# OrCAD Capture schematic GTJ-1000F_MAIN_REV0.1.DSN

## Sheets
1 00. INDEX
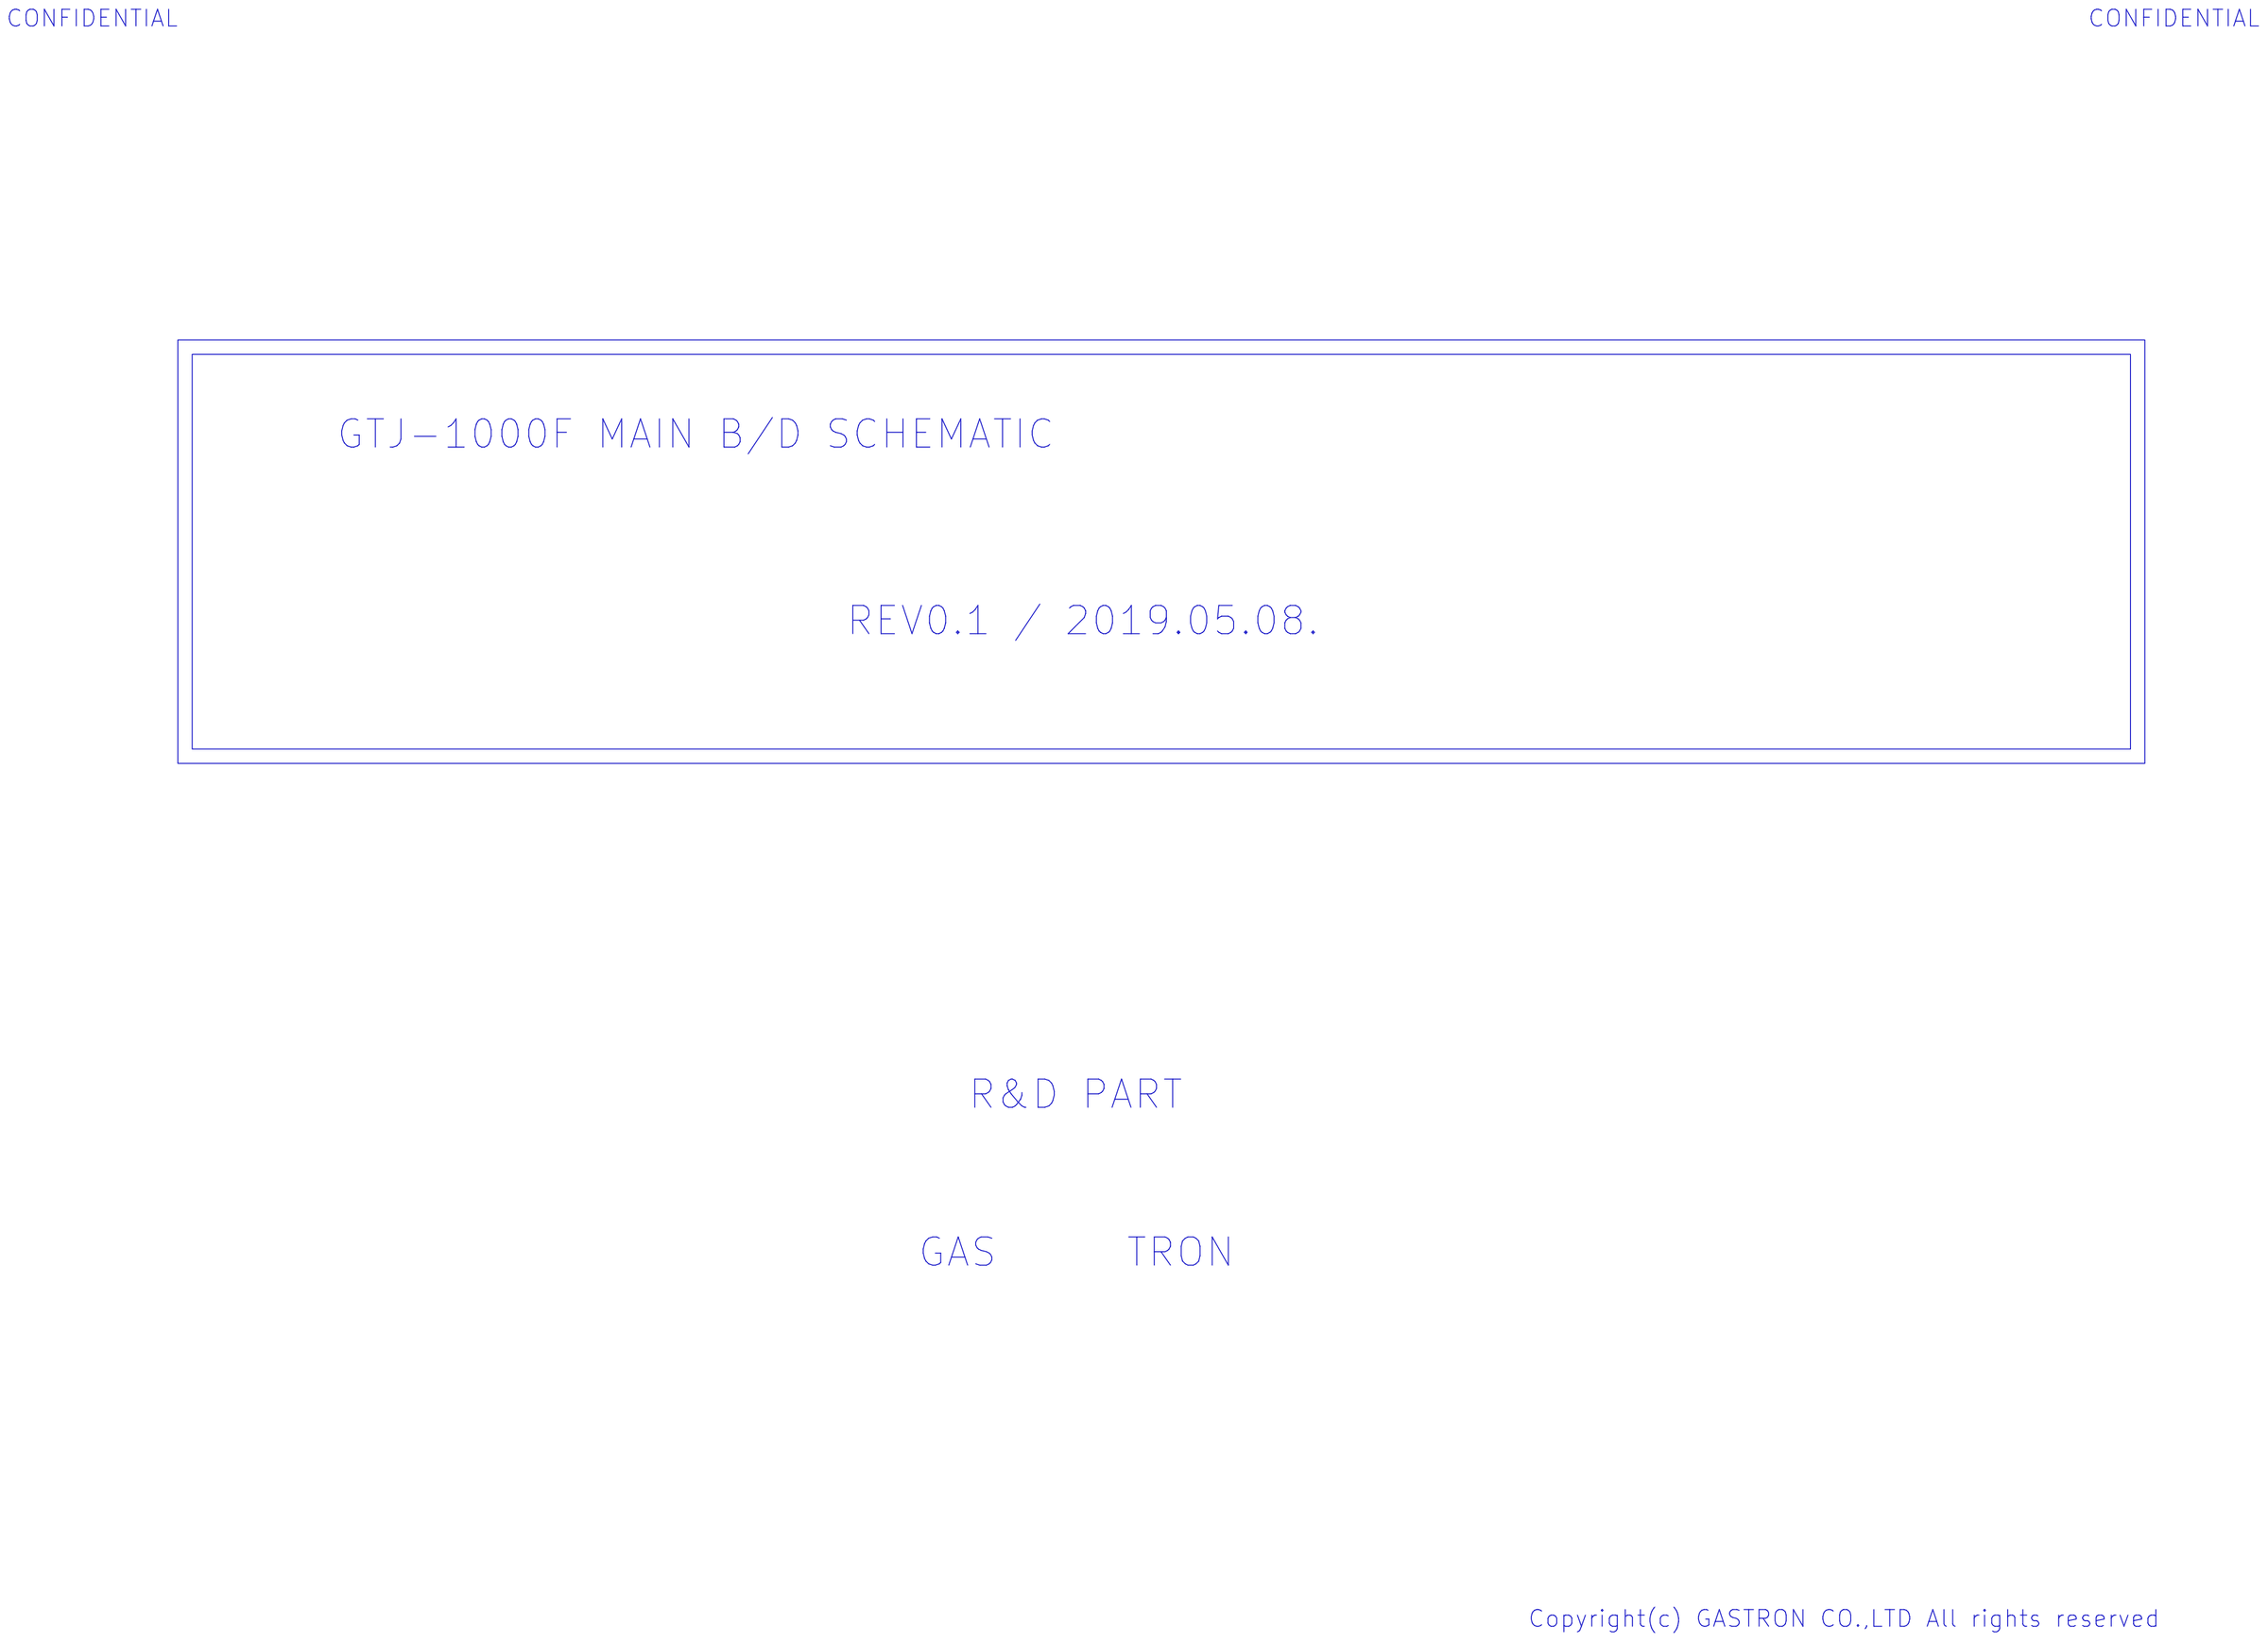
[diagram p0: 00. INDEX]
2 01. Power Supply: size A3; title: Power Supply; rev: 0.1
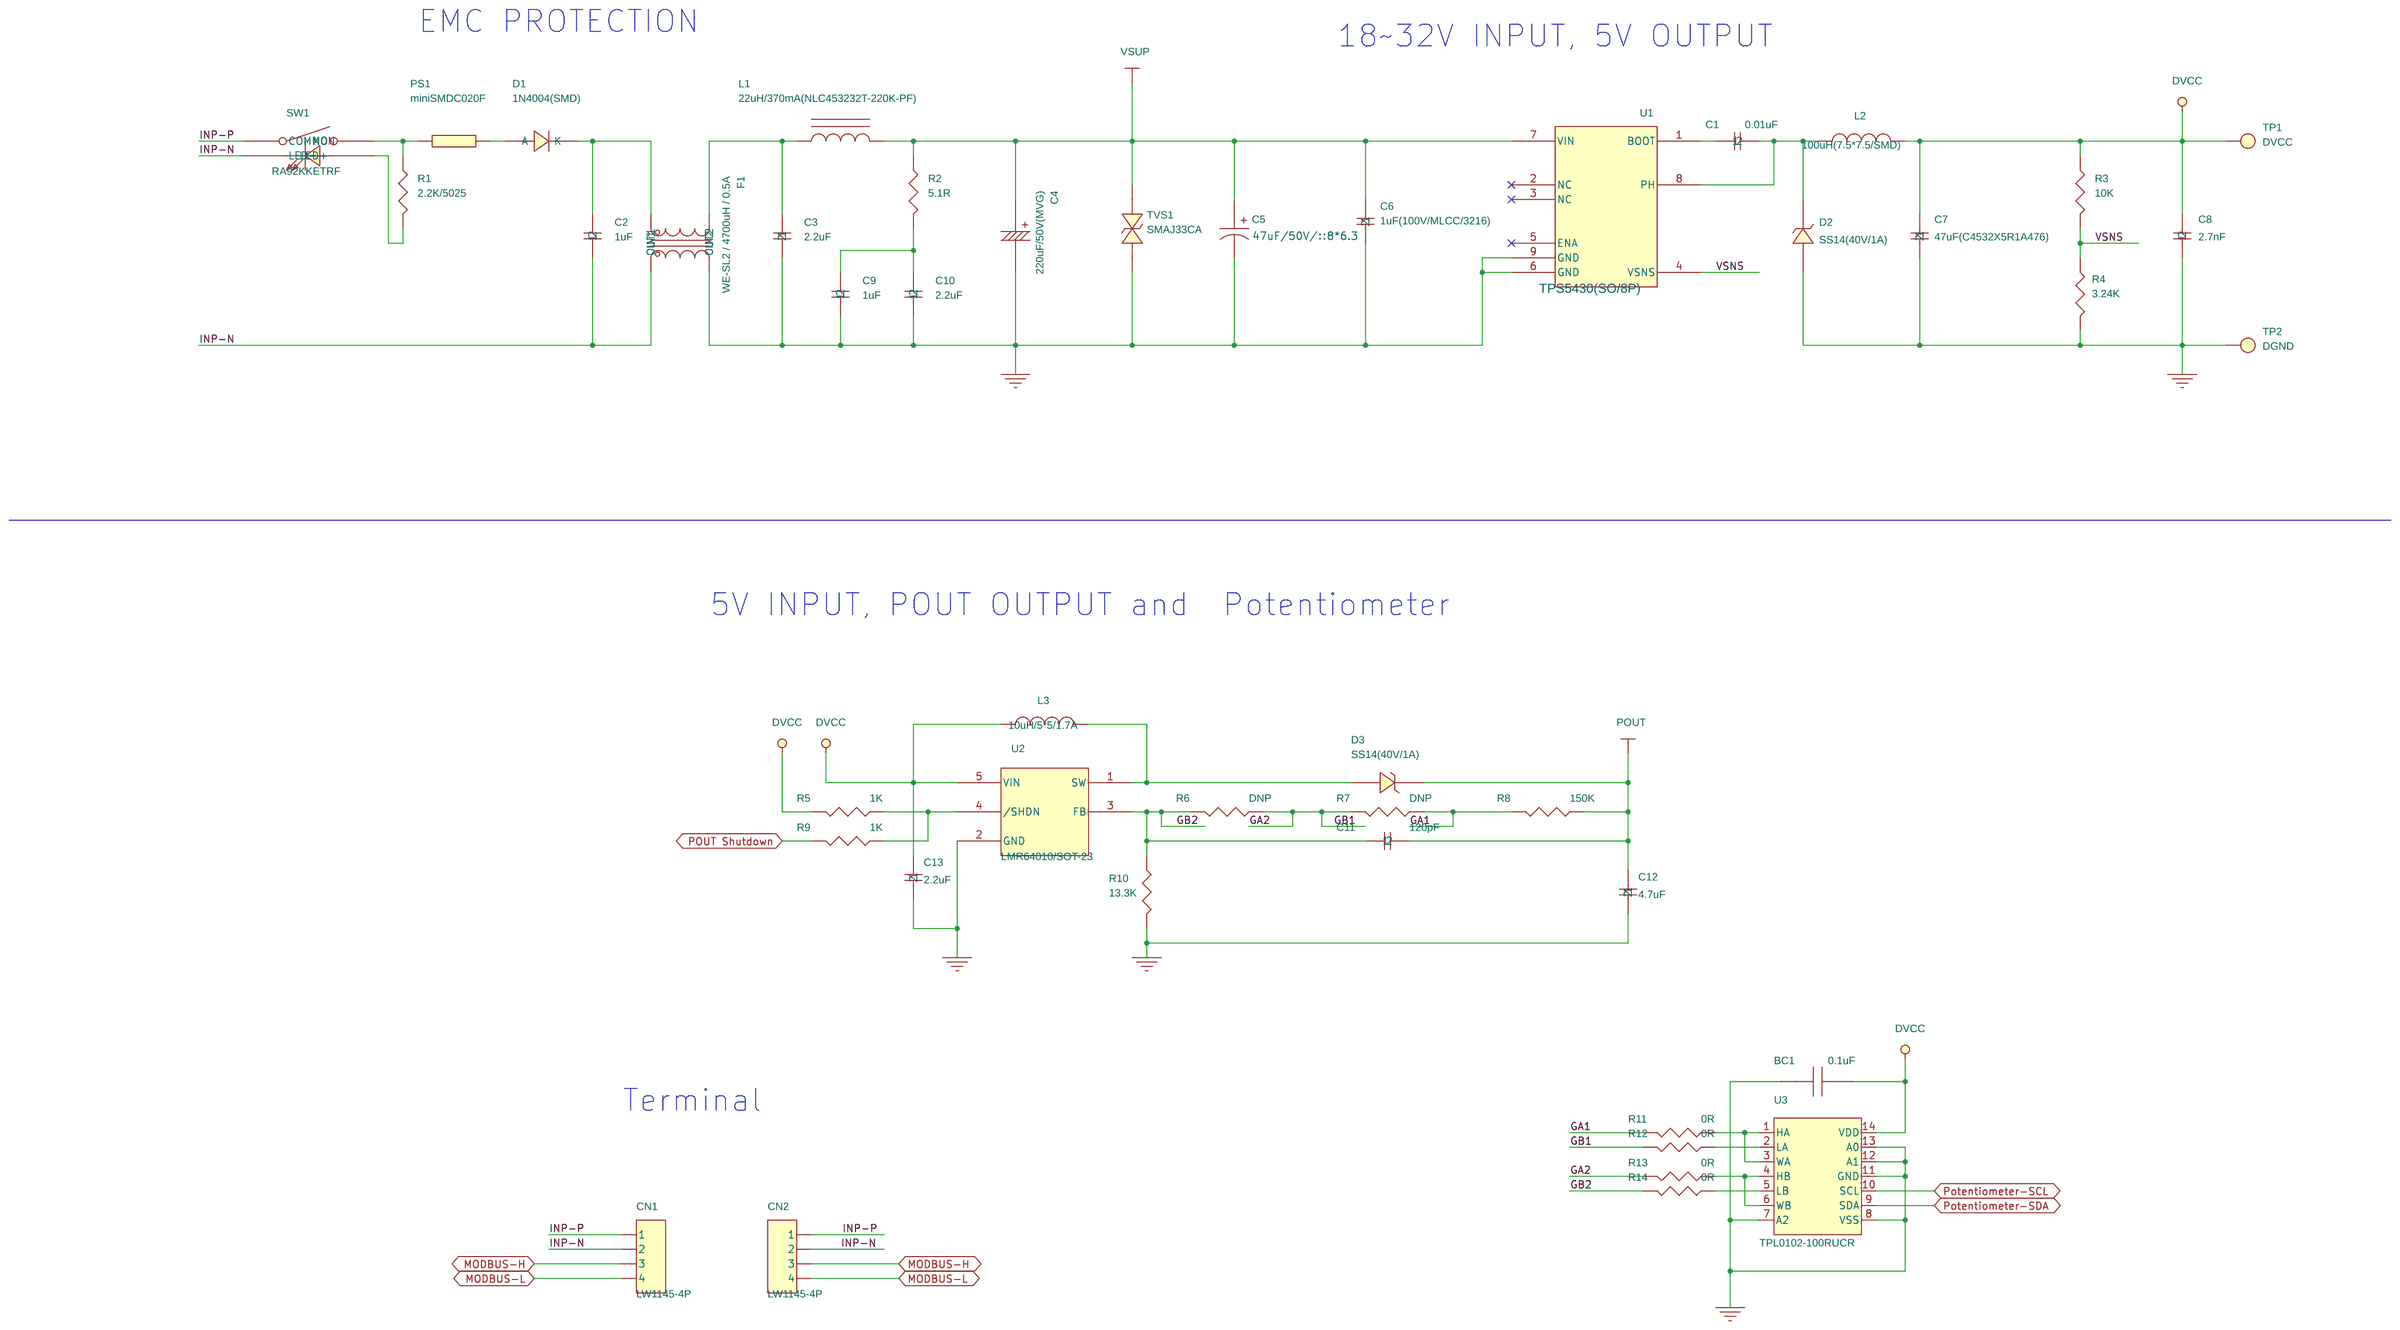
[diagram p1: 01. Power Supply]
3 02. MCU Peripheral: size A3; title: MCU Peripheral; rev: 0.1
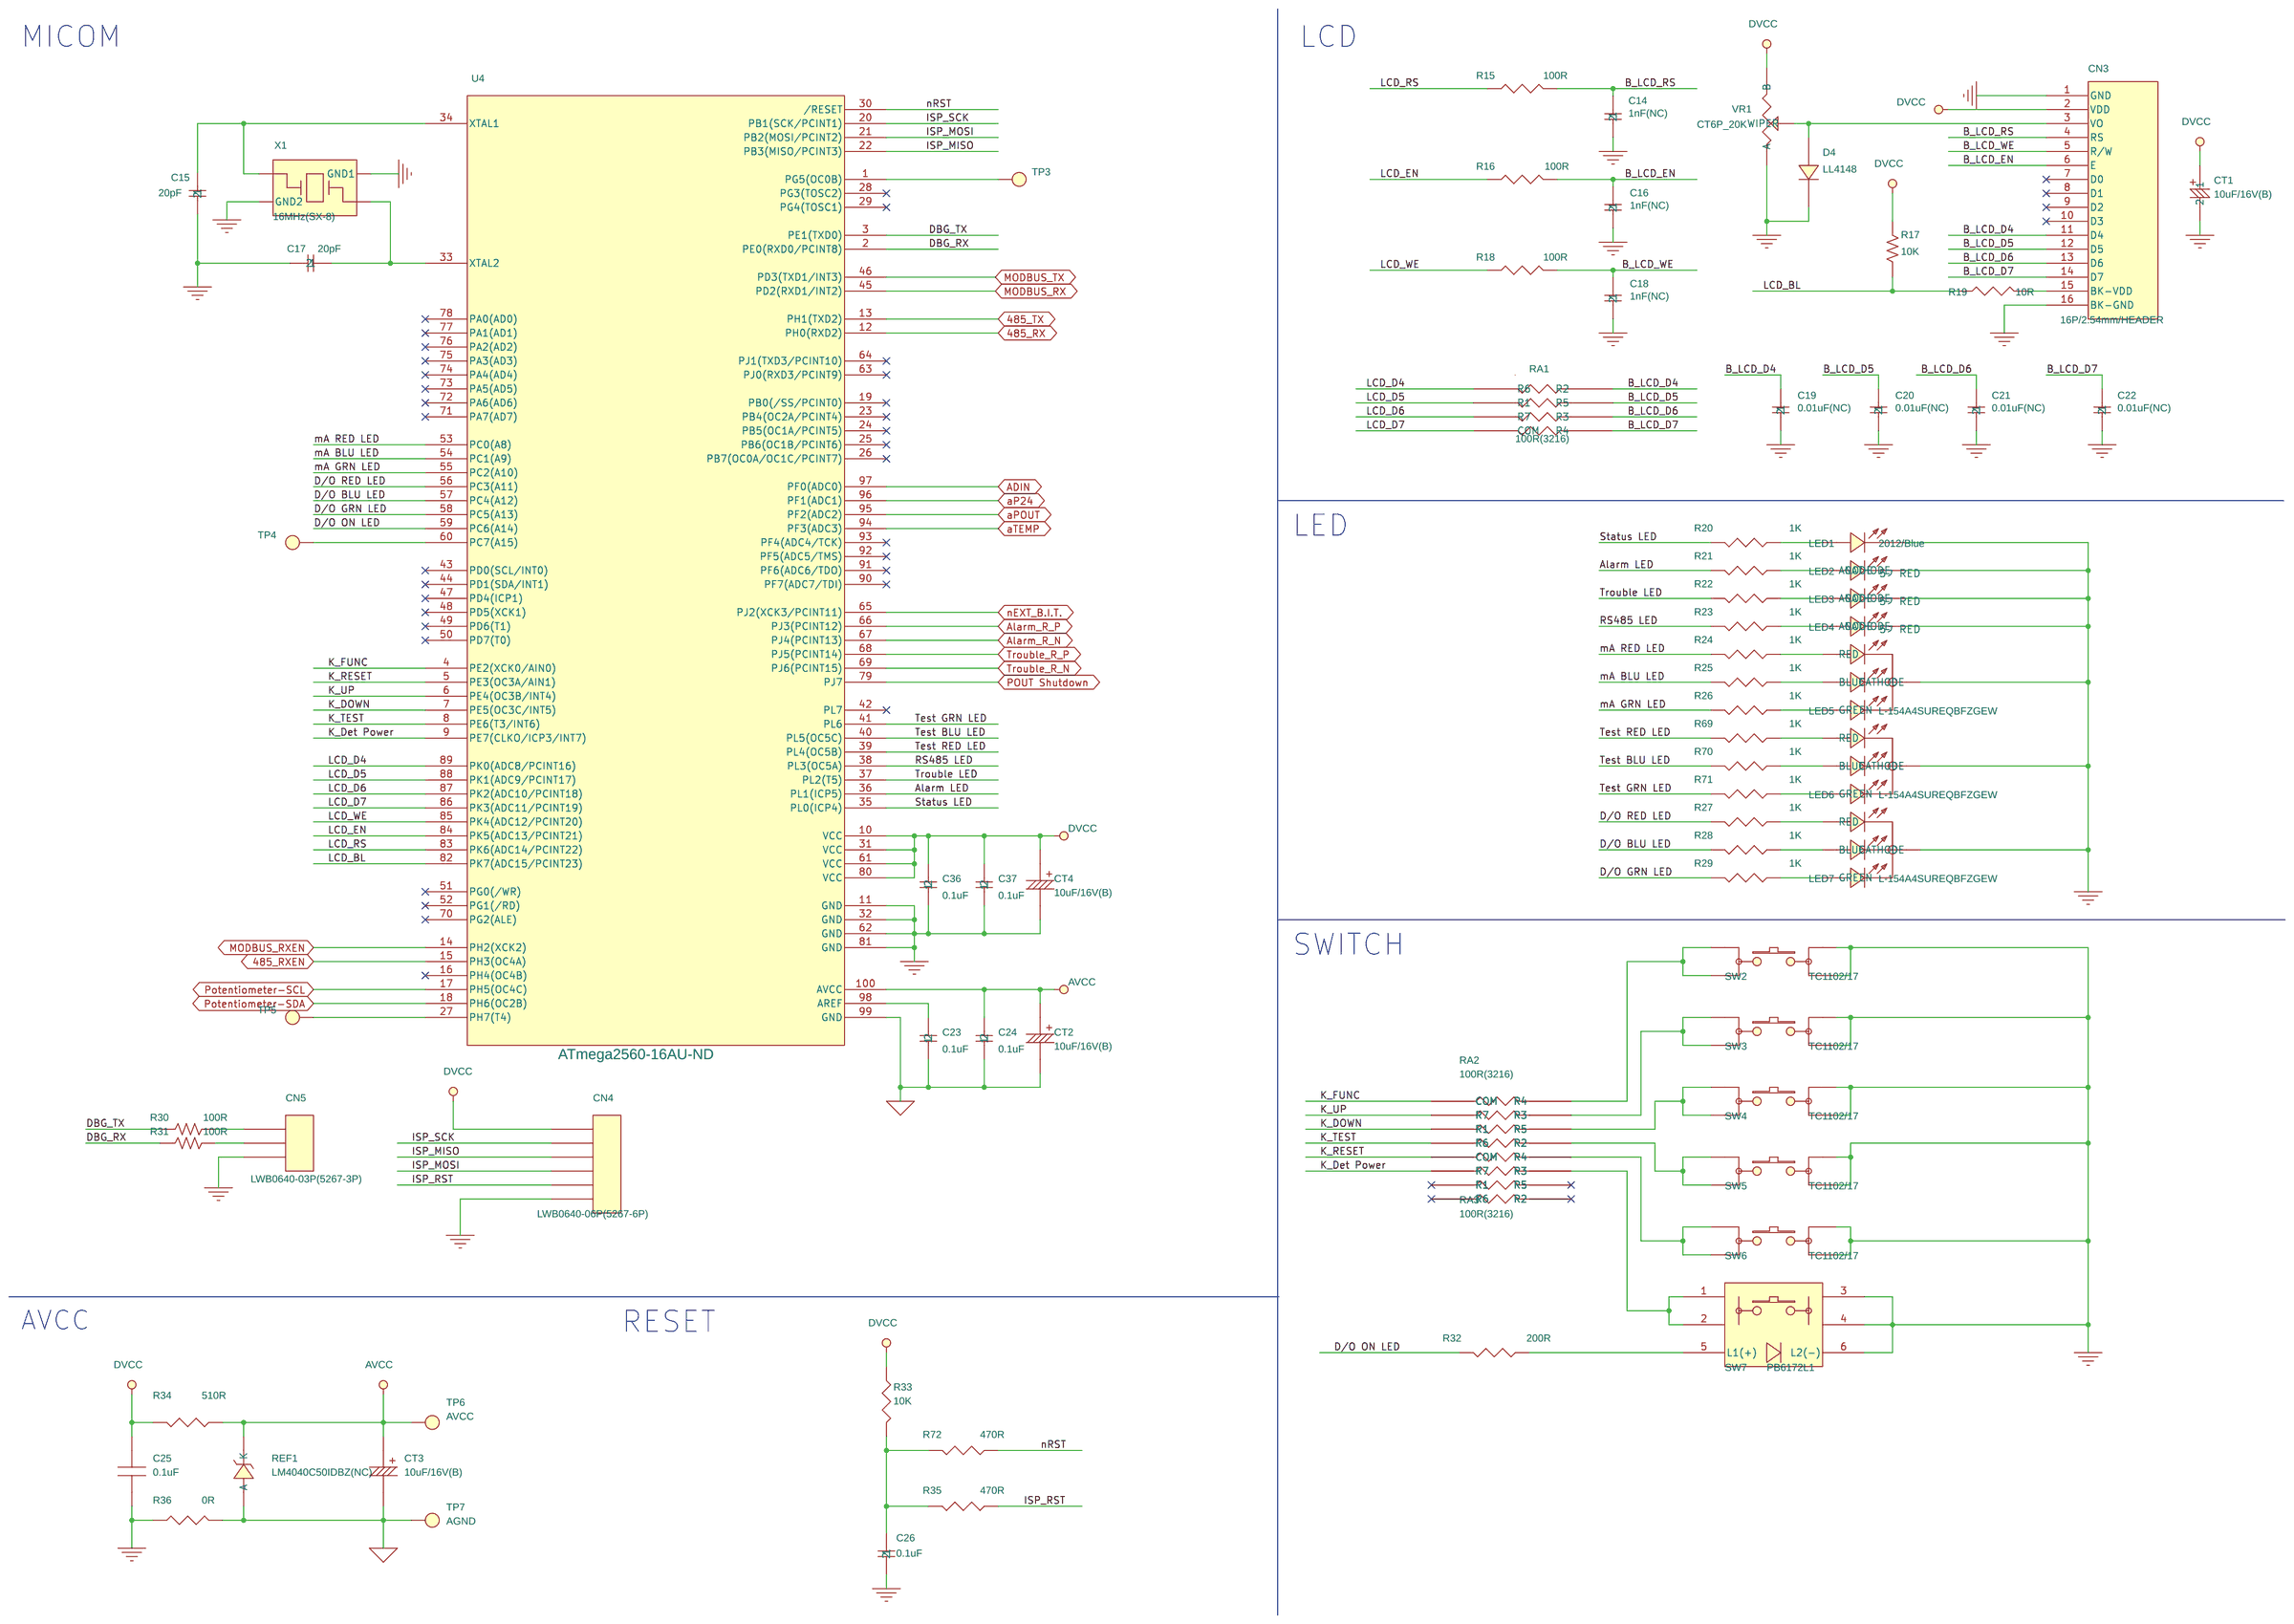
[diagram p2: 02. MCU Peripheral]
4 03. External Interface: size A3; title: External IN/OUT; rev: 0.1
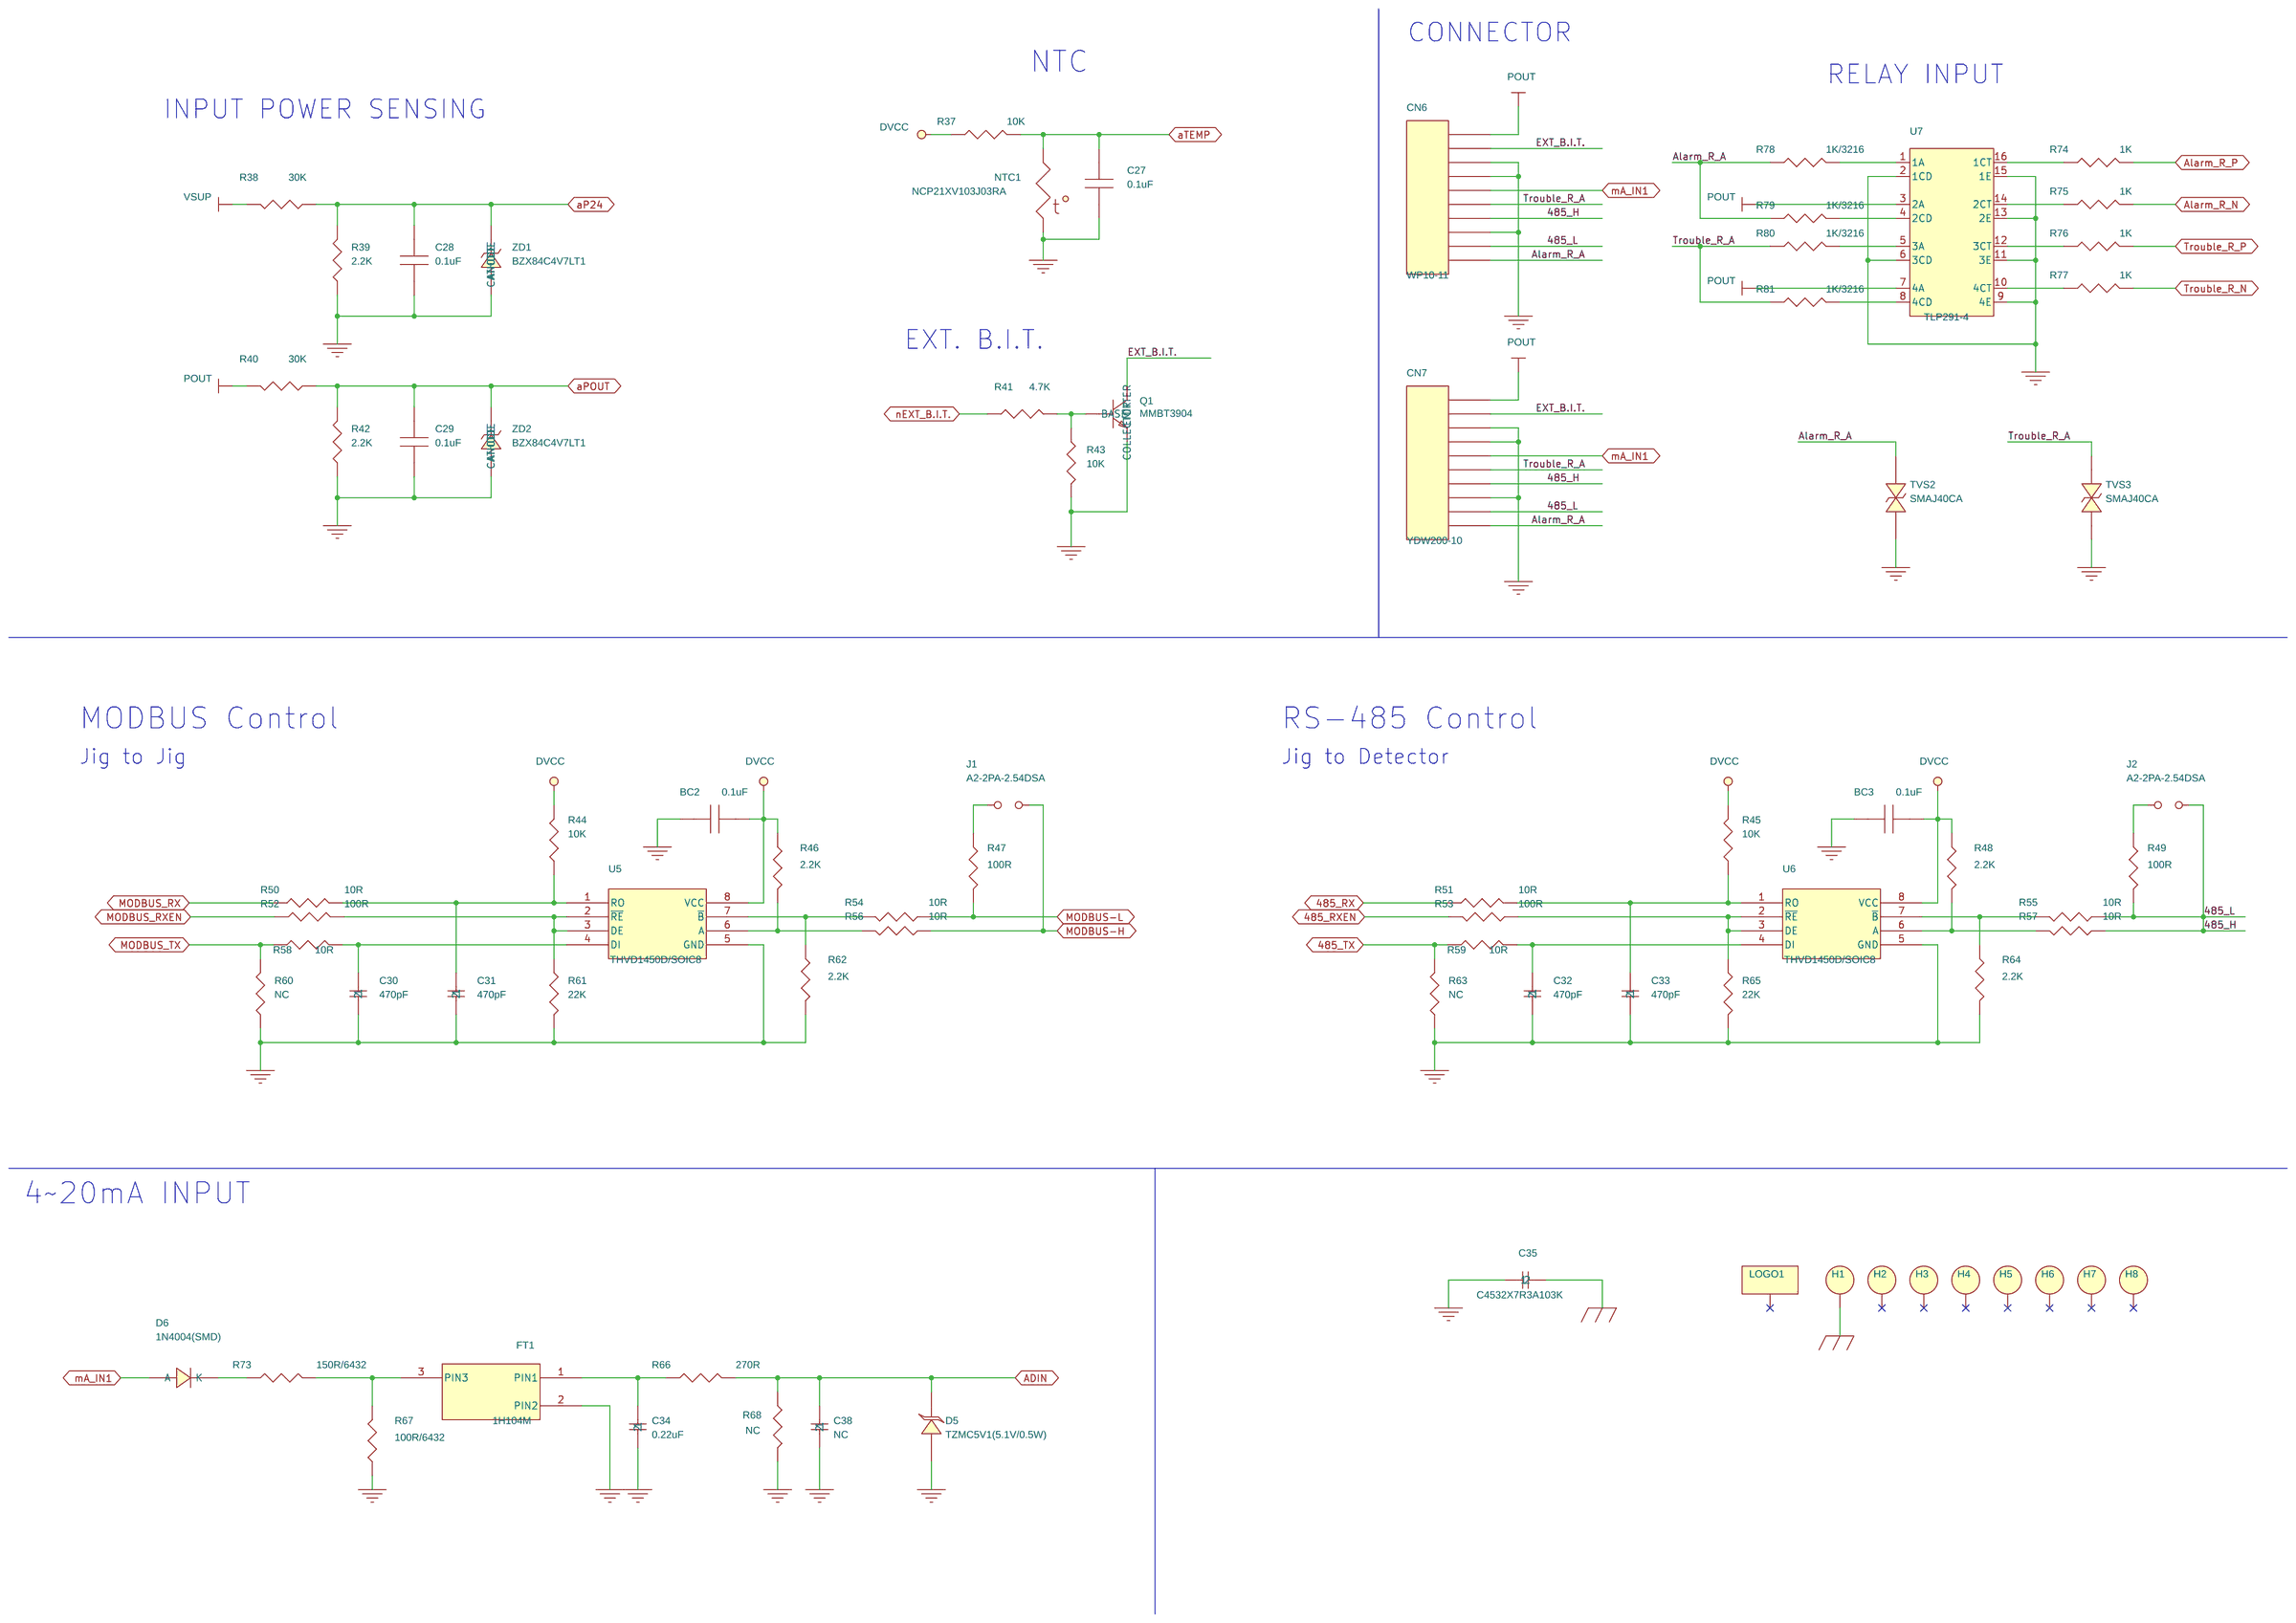
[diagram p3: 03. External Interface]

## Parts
sheet 01. Power Supply
BC1  0.1uF  [c0603]
C1  0.01uF  [C0805]
C2  1uF  [C0805]
C3  2.2uF  [C0805]
C4  220uF/50V(MVG)  [SECAP_10]
C5  47uF/50V/∷8*6.3  [SMD-ECAP-H10[TEL]]
C6  1uF(100V/MLCC/3216)  [C1206]
C7  47uF(C4532X5R1A476)  [C1812]
C8  2.7nF  [C0805]
C9  1uF  [C0805]
C10  2.2uF  [C0805]
C11  120pF  [C0805]
C12  4.7uF  [C0805]
C13  2.2uF  [C0805]
CN1  LW1145-4P  [LW1145-04]
CN2  LW1145-4P  [LW1145-04]
D1  1N4004(SMD)  [DO214AC_12]
D2  SS14(40V/1A)  [DO214AC_12]
D3  SS14(40V/1A)  [DO214AC_12]
F1  WE-SL2 / 4700uH / 0.5A  [744220-0.5]
L1  22uH/370mA(NLC453232T-220K-PF)  [L4532]
L2  100uH(7.5*7.5/SMD)  [SHP_7060P]
L3  10uH/5*5/1.7A  [YC53RT]
PS1  miniSMDC020F  [MINISMC050F]
R1  2.2K/5025  [R5025]
R2  5.1R  [R0805]
R3  10K  [R0805]
R4  3.24K  [R0805]
R5  1K  [R0805]
R6  DNP  [R0805]
R7  DNP  [R0805]
R8  150K  [R0805]
R9  1K  [R0805]
R10  13.3K  [R0805]
R11  0R  [R0805]
R12  0R  [R0805]
R13  0R  [R0805]
R14  0R  [R0805]
SW1  RA92KKETRF  [RACKER_SW]
TP1  DVCC  [tp-smd-1mm]
TP2  DGND  [tp-smd-1mm]
TVS1  SMAJ33CA  [SMA-N]
U1  TPS5430(SO/8P)  [SOIC8_150(TPS5430)]
U2  LMR64010/SOT-23  [sot23_5]
U3  TPL0102-100RUCR  [QFN14]
sheet 02. MCU Peripheral
C14  1nF(NC)  [C0805]
C15  20pF  [C0805]
C16  1nF(NC)  [C0805]
C17  20pF  [C0805]
C18  1nF(NC)  [C0805]
C19  0.01uF(NC)  [C0805]
C20  0.01uF(NC)  [C0805]
C21  0.01uF(NC)  [C0805]
C22  0.01uF(NC)  [C0805]
C23  0.1uF  [C0805]
C24  0.1uF  [C0805]
C25  0.1uF  [C0805]
C26  0.1uF  [C0805]
C36  0.1uF  [C0805]
C37  0.1uF  [C0805]
CN3  16P/2.54mm/HEADER  [lc1641]
CN4  LWB0640-06P(5267-6P)  [5267-06]
CN5  LWB0640-03P(5267-3P)  [5267-03]
CT1  10uF/16V(B)  [CT_B]
CT2  10uF/16V(B)  [CT_B]
CT3  10uF/16V(B)  [CT_B]
CT4  10uF/16V(B)  [CT_B]
D4  LL4148  [MLL34_12]
LED1  2012/Blue  [D0805_21]
LED2  5フ RED  [LED5MM_21]
LED3  5フ RED  [LED5MM_21]
LED4  5フ RED  [LED5MM_21]
LED5  L-154A4SUREQBFZGEW  [led_5mm-4p]
LED6  L-154A4SUREQBFZGEW  [led_5mm-4p]
LED7  L-154A4SUREQBFZGEW  [led_5mm-4p]
R15  100R  [r0805]
R16  100R  [r0805]
R17  10K  [R0805]
R18  100R  [r0805]
R19  10R  [r0805]
R20  1K  [r0805]
R21  1K  [r0805]
R22  1K  [r0805]
R23  1K  [r0805]
R24  1K  [r0805]
R25  1K  [r0805]
R26  1K  [r0805]
R27  1K  [r0805]
R28  1K  [r0805]
R29  1K  [r0805]
R30  100R  [R0805]
R31  100R  [R0805]
R32  200R  [r0805]
R33  10K  [R0805]
R34  510R  [R0805]
R35  470R  [R0805]
R36  0R  [R0805]
R69  1K  [r0805]
R70  1K  [r0805]
R71  1K  [r0805]
R72  470R  [R0805]
RA1  100R(3216)  [AR3216]
RA2  100R(3216)  [AR3216]
RA3  100R(3216)  [AR3216]
REF1  LM4040C50IDBZ(NC)  [SOT23_123]
SW2  TC1102/17  [st-1102-1234]
SW3  TC1102/17  [st-1102-1234]
SW4  TC1102/17  [st-1102-1234]
SW5  TC1102/17  [st-1102-1234]
SW6  TC1102/17  [st-1102-1234]
SW7  PB6172L1  [PB6171FL]
TP3  DGND  [tp-smd-1mm]
TP4  DGND  [tp-smd-1mm]
TP5  DGND  [tp-smd-1mm]
TP6  AVCC  [TP-SMD-1MM]
TP7  AGND  [TP-SMD-1MM]
U4  ATmega2560-16AU-ND  [TQFP100]
VR1  CT6P_20K  [VR-CT6P]
X1  16MHz(SX-8)  [SX-8]
sheet 03. External Interface
BC2  0.1uF  [C0805]
BC3  0.1uF  [C0805]
C27  0.1uF  [C0805]
C28  0.1uF  [C0805]
C29  0.1uF  [C0805]
C30  470pF  [c0805]
C31  470pF  [c0805]
C32  470pF  [c0805]
C33  470pF  [c0805]
C34  0.22uF  [C0805]
C35  C4532X7R3A103K  [C1812]
C38  NC  [C0805]
CN6  WP10-11  [WP10-11-4]
CN7  YDW200-10
D5  TZMC5V1(5.1V/0.5W)  [MLL34_12]
D6  1N4004(SMD)  [DO214AC_12]
FT1  1H104M  [XTAL-3PIN]
H1  CON1  [3.5mm-th]
H2  CON1  [3.5mm_10mm_nth]
H3  CON1  [3.5mm_10mm_nth]
H4  CON1  [3.5mm_10mm_nth]
H5  CON1  [3.5mm_10mm_nth]
H6  CON1  [3.5mm_10mm_nth]
H7  CON1  [3.5mm_10mm_nth]
H8  CON1  [3.5mm_10mm_nth]
J1  A2-2PA-2.54DSA  [JP2_2P54-ns]
J2  A2-2PA-2.54DSA  [JP2_2P54-ns]
LOGO1  CON1  [LOGO1]
NTC1  NCP21XV103J03RA  [R0805]
Q1  MMBT3904  [SOT23_123]
R37  10K  [R0805]
R38  30K  [R0805]
R39  2.2K  [R0805]
R40  30K  [R0805]
R41  4.7K  [R0805]
R42  2.2K  [R0805]
R43  10K  [R0805]
R44  10K  [R0805]
R45  10K  [R0805]
R46  2.2K  [r0805]
R47  100R  [r0805]
R48  2.2K  [r0805]
R49  100R  [r0805]
R50  10R  [R0805]
R51  10R  [R0805]
R52  100R  [r0805]
R53  100R  [r0805]
R54  10R  [r0805]
R55  10R  [r0805]
R56  10R  [r0805]
R57  10R  [r0805]
R58  10R  [R0805]
R59  10R  [R0805]
R60  NC  [R0805]
R61  22K  [R0805]
R62  2.2K  [r0805]
R63  NC  [R0805]
R64  2.2K  [r0805]
R65  22K  [R0805]
R66  270R  [R0805]
R67  100R/6432  [R6432]
R68  NC  [R0805]
R73  150R/6432  [R6432]
R74  1K  [R0805]
R75  1K  [R0805]
R76  1K  [R0805]
R77  1K  [R0805]
R78  1K/3216  [r1206]
R79  1K/3216  [r1206]
R80  1K/3216  [r1206]
R81  1K/3216  [r1206]
TVS2  SMAJ40CA  [SMA-N]
TVS3  SMAJ40CA  [SMA-N]
U5  THVD1450D/SOIC8  [SOIC8_150]
U6  THVD1450D/SOIC8  [SOIC8_150]
U7  TLP291-4  [SOIC16_150]
ZD1  BZX84C4V7LT1  [SOT23_123]
ZD2  BZX84C4V7LT1  [SOT23_123]

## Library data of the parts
BC1-BC3 C25 C27-C29 = C1
C1 C16 C33 = CAP_NP_6
C2 C32 = CAP_NP_5
C3 C22 = CAP_NP_10
C4 CT2-CT4 = C2
C5 = CAP_POL
C6 C38 = CAP_NP_2
C7 C14 = CAP_NP_9
C8 C35 = CAP_NP_3
C9 = CAP_NP_8
C10 C20 C30 = CAP_NP_4
C11 C37 = CAP_NP_7: COMPFIXED: NO; COMPGROUP: 0; COMPHEIGHT: 0.000; COMPKEY: NO; COMPLOC: [2845.000,-1710.000]; COMPLOCKED: NO; COMPROT: 90; COMPSIDE: TOP; DECOUPLER: NO; FPLIST: AX/.300X.100/.031,RAD/.200X.100/LS.100/.031; MEMORY: NO
C12 = CAP_NP: COMPFIXED: NO; COMPGROUP: 0; COMPHEIGHT: 0.000; COMPKEY: NO; COMPLOC: [2845.000,-1710.000]; COMPLOCKED: NO; COMPROT: 90; COMPSIDE: TOP; DECOUPLER: NO; FPLIST: AX/.300X.100/.031,RAD/.200X.100/LS.100/.031; MEMORY: NO
C13 C36 = CAP_NP_1: COMPFIXED: NO; COMPGROUP: 0; COMPHEIGHT: 0.000; COMPKEY: NO; COMPLOC: [2845.000,-1710.000]; COMPLOCKED: NO; COMPROT: 90; COMPSIDE: TOP; DECOUPLER: NO; FPLIST: AX/.300X.100/.031,RAD/.200X.100/LS.100/.031; MEMORY: NO
CN1 = CON4
CN2 = CON4_1
D1 D6 = DIODE_0
D2 D3 = DIODE_ZENER_1
F1 = TRNSFMR_67125450_1
L1 = INDUCTOR_IRON
L2 L3 = INDUCTOR
PS1 = R2
R1-R16 R18-R29 R32 R34 R36-R65 R69-R71 R74-R81 = R
SW1 = RA92KKETRF
TP1-TP7 = T_POINT_R
TVS1-TVS3 = DIODE_BI-DIR_TRIG
U1 = TPS5410_2
U2 = LMR64010_SOT-23
U3 = TPL0102
C15 = CAP_NP_8: COMPFIXED: NO; COMPGROUP: 0; COMPHEIGHT: 0.000; COMPKEY: NO; COMPLOC: [2845.000,-1710.000]; COMPLOCKED: NO; COMPROT: 90; COMPSIDE: TOP; DECOUPLER: NO; FPLIST: AX/.300X.100/.031,RAD/.200X.100/LS.100/.031; MEMORY: NO
C17 = CAP_NP_3: COMPFIXED: NO; COMPGROUP: 0; COMPHEIGHT: 0.000; COMPKEY: NO; COMPLOC: [2845.000,-1710.000]; COMPLOCKED: NO; COMPROT: 90; COMPSIDE: TOP; DECOUPLER: NO; FPLIST: AX/.300X.100/.031,RAD/.200X.100/LS.100/.031; MEMORY: NO
C18 = CAP_NP_13
C19 C31 = CAP_NP
C21 = CAP_NP_12
C23 = CAP_NP_11: COMPFIXED: NO; COMPGROUP: 0; COMPHEIGHT: 0.000; COMPKEY: NO; COMPLOC: [2845.000,-1710.000]; COMPLOCKED: NO; COMPROT: 90; COMPSIDE: TOP; DECOUPLER: NO; FPLIST: AX/.300X.100/.031,RAD/.200X.100/LS.100/.031; MEMORY: NO
C24 = CAP_NP_2: COMPFIXED: NO; COMPGROUP: 0; COMPHEIGHT: 0.000; COMPKEY: NO; COMPLOC: [2845.000,-1710.000]; COMPLOCKED: NO; COMPROT: 90; COMPSIDE: TOP; DECOUPLER: NO; FPLIST: AX/.300X.100/.031,RAD/.200X.100/LS.100/.031; MEMORY: NO
C26 = CAP_NP_5: COMPFIXED: NO; COMPGROUP: 0; COMPHEIGHT: 0.000; COMPKEY: NO; COMPLOC: [2845.000,-1710.000]; COMPLOCKED: NO; COMPROT: 90; COMPSIDE: TOP; DECOUPLER: NO; FPLIST: AX/.300X.100/.031,RAD/.200X.100/LS.100/.031; MEMORY: NO
CN3 = GT_LCD_CON
CN4 = CON6
CN5 = CON3
CT1 = CAP_ELEC: 1ST PART FIELD: C10; COMPFIXED: NO; COMPGROUP: 0; COMPHEIGHT: 0.000; COMPKEY: NO; COMPLOC: [200.000,1400.000]; COMPLOCKED: NO; COMPROT: 0; COMPSIDE: TOP; DECOUPLER: NO; FPLIST: RAD/.200X.100/LS.100/.031,CPCYL1/D.200/LS.100/.031,RAD/.300X.100/LS.200/.031,CPCYL1/D.500/LS.200/.040,CYL/D.400/LS.200/.034; MEMORY: NO
D4 = DIODE_7
LED1 = LED
LED2-LED4 = LED_2
LED5-LED7 = LED_Multi_L-154A4SUREQBFZGEW
R17 R30 R31 = R_v4
R33 R35 R66-R68 R72 R73 = R: 1ST PART FIELD: RES; COMPFIXED: NO; COMPGROUP: 0; COMPHEIGHT: 0.000; COMPKEY: NO; COMPLOC: [3525.000,375.000]; COMPLOCKED: NO; COMPROT: 90; COMPSIDE: TOP; DECOUPLER: NO; FPLIST: AX/.400X.100/.031,AX/.375X.100/.031; MEMORY: NO
RA1-RA3 = RA4_0
REF1 = DIODE_ZENER_0
SW2-SW6 = SW_PUSHBUTTON-SPST-2_SM_1
SW7 = PB167
U4 = ATmega1280_1
VR1 = RESISTOR_VAR_0
X1 = CRYSTAL_SX-8
C34 = CAP_NP_1
CN6 CN7 = CON10
D5 = DIODE_TAZ_3
FT1 = 1H104M
H1-H8 = CON1_2
J1 J2 = JUMPER_1
LOGO1 = CON1_3
NTC1 = THERMISTOR
Q1 = NPN_1
U5 U6 = MAX485_0
U7 = TLP291-4
ZD1 ZD2 = ZENER_0

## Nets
AVCC: C24.2 CT2.1 CT3.1 R34.2 REF1.1(K) TP6.1(TP) U4.100(AVCC)
DVCC: BC1.1 BC2.1 BC3.1 C7.1 C8.2 C13.1 C25.1 C36.2 C37.2 CN3.2(VDD) CN4.1 CT1.1 CT4.1 L2.2 L3.1 R3.1 R5.2 R17.2 R33.1 R34.1 R37.1 R44.2 R45.2 R46.1 R48.1 TP1.1(TP) U2.5(VIN) U3.14(VDD) U4.10(VCC) U4.31(VCC) U4.61(VCC) U4.80(VCC) U5.8(VCC) U6.8(VCC) VR1.1(B)
GND: BC1.2 BC2.2 BC3.2 C3.2 C4.2 C5.2 C6.2 C7.2 C8.1 C9.1 C10.1 C12.2 C13.2 C14.2 C15.2 C16.2 C17.2 C18.2 C19.2 C20.2 C21.2 C22.2 C25.2 C26.2 C27.2 C28.2 C29.2 C30.2 C31.2 C32.2 C33.2 C34.2 C35.1 C36.1 C37.1 C38.2 CN3.1(GND) CN3.16(BK-GND) CN4.6 CN5.3 CN6.3 CN6.4 CN6.8 CN7.3 CN7.4 CN7.8 CT1.2 CT4.2 D2.2 D4.1(K) D5.2 F1.3(OUT2) FT1.2(PIN2) LED1.2(CATHODE) LED2.2(CATHODE) LED3.2(CATHODE) LED4.2(CATHODE) LED5.2(CATHODE) LED6.2(CATHODE) LED7.2(CATHODE) NTC1.2 Q1.2(EMITTER) R4.2 R10.2 R36.1 R39.2 R42.2 R43.2 R60.1 R61.2 R62.2 R63.1 R64.2 R65.2 R67.2 R68.1 SW2.3 SW2.4 SW3.3 SW3.4 SW4.3 SW4.4 SW5.3 SW5.4 SW6.3 SW6.4 SW7.3 SW7.4 SW7.6(L2(-)) TP2.1(TP) TVS1.1 TVS2.1 TVS3.1 U1.6(GND) U1.9(GND) U2.2(GND) U3.7(A2) U3.8(VSS) U3.11(GND) U3.12(A1) U3.13(A0) U4.11(GND) U4.32(GND) U4.62(GND) U4.81(GND) U5.5(GND) U6.5(GND) U7.2(1CD) U7.6(3CD) U7.9(4E) U7.11(3E) U7.13(2E) U7.15(1E) VR1.3(A) X1.2(GND1) X1.4(GND2) ZD1.1(ANODE) ZD2.1(ANODE)
GND_EARTH: C35.2 H1.1
GND_SIGNAL: C23.1 C24.1 CT2.2 CT3.2 R36.2 REF1.2(A) TP7.1(TP) U4.99(GND)
485_H: CN6.7 CN7.7 J2.1 R57.1
485_L: CN6.9 CN7.9 R49.2 R55.1
485_RX: R51.1 U4.12(PH0(RXD2))
485_RXEN: R53.2 U4.15(PH3(OC4A))
485_TX: R59.2 R63.2 U4.13(PH1(TXD2))
ADIN: C38.1 D5.1 R66.1 R68.2 U4.97(PF0(ADC0))
Alarm LED: R21.2 U4.36(PL1(ICP5))
Alarm_R_A: CN6.10 CN7.10 R78.1 R79.1 TVS2.2
Alarm_R_N: R75.2 U4.67(PJ4(PCINT13))
Alarm_R_P: R74.2 U4.66(PJ3(PCINT12))
aP24: C28.1 R38.2 R39.1 U4.96(PF1(ADC1)) ZD1.3(CATHODE)
aPOUT: C29.1 R40.2 R42.1 U4.95(PF2(ADC2)) ZD2.3(CATHODE)
aTEMP: C27.1 NTC1.1 R37.2 U4.94(PF3(ADC3))
B_LCD_D4: C19.1 CN3.11(D4) RA1.5(R2)
B_LCD_D5: C20.1 CN3.12(D5) RA1.6(R5)
B_LCD_D6: C21.1 CN3.13(D6) RA1.7(R3)
B_LCD_D7: C22.1 CN3.14(D7) RA1.8(R4)
B_LCD_EN: C16.1 CN3.6(E) R16.2
B_LCD_RS: C14.1 CN3.4(RS) R15.2
B_LCD_WE: C18.1 CN3.5(R/W) R18.2
D/O BLU LED: R28.2 U4.57(PC4(A12))
D/O GRN LED: R29.2 U4.58(PC5(A13))
D/O ON LED: R32.2 U4.59(PC6(A14))
D/O RED LED: R27.2 U4.56(PC3(A11))
DBG_RX: R31.1 U4.2(PE0(RXD0/PCINT8))
DBG_TX: R30.1 U4.3(PE1(TXD0))
EXT_B.I.T.: CN6.2 CN7.2 Q1.3(COLLECTOR)
GA1: R7.1 R8.2 R11.2
GA2: R6.1 R7.2 R12.2 R13.2
GB2: C11.1 R6.2 R10.1 R14.2 U2.3(FB)
INP-N: C2.1 CN1.2 CN2.2 F1.2(OUT1) SW1.4(LED-)
INP-P: CN1.1 CN2.1 SW1.1(COMMON)
ISP_MISO: CN4.3 U4.22(PB3(MISO/PCINT3))
ISP_MOSI: CN4.4 U4.21(PB2(MOSI/PCINT2))
ISP_RST: CN4.5 R35.1
ISP_SCK: CN4.2 U4.20(PB1(SCK/PCINT1))
K_Det Power: RA3.2(R7) U4.9(PE7(CLKO/ICP3/INT7))
K_DOWN: RA2.3(R1) U4.7(PE5(OC3C/INT5))
K_FUNC: RA2.1(COM) U4.4(PE2(XCK0/AIN0))
K_RESET: RA3.1(COM) U4.5(PE3(OC3A/AIN1))
K_TEST: RA2.4(R6) U4.8(PE6(T3/INT6))
K_UP: RA2.2(R7) U4.6(PE4(OC3B/INT4))
LCD_BL: R17.1 R19.1 U4.82(PK7(ADC15/PCINT23))
LCD_D4: RA1.4(R6) U4.89(PK0(ADC8/PCINT16))
LCD_D5: RA1.3(R1) U4.88(PK1(ADC9/PCINT17))
LCD_D6: RA1.2(R7) U4.87(PK2(ADC10/PCINT18))
LCD_D7: RA1.1(COM) U4.86(PK3(ADC11/PCINT19))
LCD_EN: R16.1 U4.84(PK5(ADC13/PCINT21))
LCD_RS: R15.1 U4.83(PK6(ADC14/PCINT22))
LCD_WE: R18.1 U4.85(PK4(ADC12/PCINT20))
mA BLU LED: R25.2 U4.54(PC1(A9))
mA GRN LED: R26.2 U4.55(PC2(A10))
mA RED LED: R24.2 U4.53(PC0(A8))
mA_IN1: CN6.5 CN7.5 D6.2(A)
MODBUS-H: CN1.3 CN2.3 J1.1 R56.1
MODBUS-L: CN1.4 CN2.4 R47.2 R54.1
MODBUS_RX: R50.1 U4.45(PD2(RXD1/INT2))
MODBUS_RXEN: R52.2 U4.14(PH2(XCK2))
MODBUS_TX: R58.2 R60.2 U4.46(PD3(TXD1/INT3))
nEXT_B.I.T.: R41.1 U4.65(PJ2(XCK3/PCINT11))
nRST: R72.1 U4.30(/RESET)
Potentiometer-SCL: U3.10(SCL) U4.17(PH5(OC4C))
Potentiometer-SDA: U3.9(SDA) U4.18(PH6(OC2B))
POUT: C11.2 C12.1 CN6.1 CN7.1 D3.1 R8.1 R40.1 U7.3(2A) U7.7(4A)
POUT Shutdown: R9.2 U4.79(PJ7)
RS485 LED: R23.2 U4.38(PL3(OC5A))
Status LED: R20.2 U4.35(PL0(ICP4))
Test BLU LED: R70.2 U4.40(PL5(OC5C))
Test GRN LED: R71.2 U4.41(PL6)
Test RED LED: R69.2 U4.39(PL4(OC5B))
Trouble LED: R22.2 U4.37(PL2(T5))
Trouble_R_A: CN6.6 CN7.6 R80.1 R81.1 TVS3.2
Trouble_R_N: R77.2 U4.69(PJ6(PCINT15))
Trouble_R_P: R76.2 U4.68(PJ5(PCINT14))
VSNS: R3.2 R4.1 U1.4(VSNS)
VSUP: C4.1 C5.1 C6.1 L1.2 R2.1 R38.1 TVS1.2 U1.7(VIN)
N3791830: C1.1 U1.1(BOOT)
N3791834: C1.2 D2.1 L2.1 U1.8(PH)
N3795891: R5.1 R9.1 U2.4(/SHDN)
N3796723: D3.2 L3.2 U2.1(SW)
N3798628: R11.1 U3.1(HA) U3.3(WA)
N3802003: C15.1 U4.34(XTAL1) X1.1
N3802219: C17.1 U4.33(XTAL2) X1.3
N3806206: CN3.15(BK-VDD) R19.2
N3814909: C26.1 R33.2 R35.2 R72.2
N3820428: C34.1 FT1.1(PIN1) R66.2
N3820558: FT1.3(PIN3) R67.1 R73.1
N3829255: C30.1 R58.1 U5.4(DI)
N3829271: R52.1 R61.1 U5.2(~{RE}) U5.3(DE)
N3829283: C31.1 R44.1 R50.2 U5.1(RO)
N3829511: R46.2 R56.2 U5.6(A)
N3836904: C32.1 R59.1 U6.4(DI)
N3836920: R53.1 R65.1 U6.2(~{RE}) U6.3(DE)
N3836932: C33.1 R45.1 R51.2 U6.1(RO)
N3837160: R48.2 R57.2 U6.6(A)
N3840753: J2.2 R49.1
N3841145: J1.2 R47.1
N3845996: R13.1 U3.4(HB) U3.6(WB)
N3852690: C3.1 F1.4(IN2) L1.1
N3852778: C9.2 C10.2 R2.2
N3852932: C2.2 D1.1(K) F1.1(IN1)
N3852972: D1.2(A) PS1.2
N3862317: CN5.1 R30.2
N3862321: CN5.2 R31.2
N3866792: LED1.1(ANODE) R20.1
N3867612: LED2.1(ANODE) R21.1
N3867616: LED3.1(ANODE) R22.1
N3867620: LED4.1(ANODE) R23.1
N3870850: R54.2 R62.1 U5.7(~{B})
N3871371: R55.2 R64.1 U6.7(~{B})
N3883159: R14.1 U3.5(LB)
N3884993: R12.1 U3.2(LA)
N3885948: Q1.1(BASE) R41.2 R43.1
N3887624: PS1.1 R1.1 SW1.2(NO)
N3888697: R1.2 SW1.3(LED+)
N3893985: C23.2 U4.98(AREF)
N3898798: CN3.3(VO) D4.2(A) VR1.2(WIPER)
N3904240: RA2.8(R4) SW2.1 SW2.2
N3904272: RA2.7(R3) SW3.1 SW3.2
N3904340: RA2.5(R2) SW5.1 SW5.2
N3905453: RA3.8(R4) SW6.1 SW6.2
N3905611: RA2.6(R5) SW4.1 SW4.2
N3910126: LED5.1(RED) R24.1
N3910130: LED5.3(BLUE) R25.1
N3910134: LED5.4(GREEN) R26.1
N3917763: TP5.1(TP) U4.27(PH7(T4))
N3917841: TP3.1(TP) U4.1(PG5(OC0B))
N3917905: TP4.1(TP) U4.60(PC7(A15))
N3945533: LED7.1(RED) R27.1
N3945537: LED7.3(BLUE) R28.1
N3945541: LED7.4(GREEN) R29.1
N3945704: LED6.1(RED) R69.1
N3945730: LED6.3(BLUE) R70.1
N3945756: LED6.4(GREEN) R71.1
N3953427: RA3.7(R3) SW7.1 SW7.2
N3953500: R32.1 SW7.5(L1(+))
N3966848: D6.1(K) R73.2
N3986249: R74.1 U7.16(1CT)
N3987743: R75.1 U7.14(2CT)
N3987755: R76.1 U7.12(3CT)
N3987767: R77.1 U7.10(4CT)
N3988257: R78.2 U7.1(1A)
N3988670: R79.2 U7.4(2CD)
N3988792: R80.2 U7.5(3A)
N3988804: R81.2 U7.8(4CD)

Not connected (* = marked no-connect by the designer): CN3 7(D0)* 8(D1)* 9(D2)* 10(D3)*; H2 1*; H3 1*; H4 1*; H5 1*; H6 1*; H7 1*; H8 1*; LOGO1 1*; RA3 3(R1)* 4(R6)* 5(R2)* 6(R5)*; U1 2(NC)* 3(NC)* 5(ENA)*; U4 16(PH4(OC4B))* 19(PB0(/SS/PCINT0))* 23(PB4(OC2A/PCINT4))* 24(PB5(OC1A/PCINT5))* 25(PB6(OC1B/PCINT6))* 26(PB7(OC0A/OC1C/PCINT7))* 28(PG3(TOSC2))* 29(PG4(TOSC1))* 42(PL7)* 43(PD0(SCL/INT0))* 44(PD1(SDA/INT1))* 47(PD4(ICP1))* 48(PD5(XCK1))* 49(PD6(T1))* 50(PD7(T0))* 51(PG0(/WR))* 52(PG1(/RD))* 63(PJ0(RXD3/PCINT9))* 64(PJ1(TXD3/PCINT10))* 70(PG2(ALE))* 71(PA7(AD7))* 72(PA6(AD6))* 73(PA5(AD5))* 74(PA4(AD4))* 75(PA3(AD3))* 76(PA2(AD2))* 77(PA1(AD1))* 78(PA0(AD0))* 90(PF7(ADC7/TDI))* 91(PF6(ADC6/TDO))* 92(PF5(ADC5/TMS))* 93(PF4(ADC4/TCK))*

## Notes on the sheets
sheet 1
- CONFIDENTIAL
- CONFIDENTIAL
- GTJ-1000F MAIN B/D SCHEMATIC
- REV0.1 / 2019.05.08.
- R&D PART
- GAS
- TRON
- Copyright(c) GASTRON CO.,LTD All rights reserved
sheet 2
- EMC PROTECTION
- 18~32V INPUT, 5V OUTPUT
- 5V INPUT, POUT OUTPUT and  Potentiometer
- Terminal
sheet 3
- MICOM
- LCD
- LED
- SWITCH
- AVCC
- RESET
sheet 4
- CONNECTOR
- NTC
- RELAY INPUT
- INPUT POWER SENSING
- EXT. B.I.T.
- MODBUS Control
- RS-485 Control
- Jig to Jig
- Jig to Detector
- 4~20mA INPUT
